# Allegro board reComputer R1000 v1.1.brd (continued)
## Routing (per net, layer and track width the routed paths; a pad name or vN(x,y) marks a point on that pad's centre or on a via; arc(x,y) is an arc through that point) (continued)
GND_ISO: length 185.1
  TOP w0.305: v1(85.85,15.4) 85.57,15.12 C138.2 ; v1(93.32,15.53) 93.32,15.4 94.19,14.54 D39.1 ; D34.1 v1(68.74,17.43) ; C141.2 74.55,14.99 v1(74.96,15.4) ; C143.2 v1(63.91,13.15)
  TOP w0.375: 68.65,10.76 R149.2 ; R149.2 69.35,11.46 ; R149.2 70.05,10.76 ; 74.94,14.51 C141.2 74.55,14.09 ; J21.3 98.48,6 ; J21.3 95.97,6 ; J21.3 97.22,4.74 ; J21.3 97.22,7.26 ; J23.3 74.98,6 ; J23.3 72.47,6 ; J23.3 73.72,4.74 ; J23.3 73.72,7.26 ; 85.88,9.87 D44.1 ; D44.1 84.61,11.26 ; D44.1 87.15,11.26 ; 85.57,13.8 C138.2 85.97,14.21 ; 94.67,13.27 D39.1 96.07,14.54 ; 85.47,4.74 J22.3 ; J22.3 84.22,6 ; J22.3 85.47,7.26 ; J22.3 86.73,6 ; 87.16,10.63 R132.2 88.56,10.63 ; 68.6,10.76 C134.2 67.9,11.46
  TOP w0.508: D44.1 85.27,10.65 v1(85.27,9.69) ; R141.2 v1(76.33,9.53) ; R132.2 v1(87.86,9.72) ; D48.1 v1(68.96,4.03)
  LYR2_GND w0.375: 72.47,6 J23.3 ; J23.3 73.72,7.26 ; J23.3 73.72,4.74 ; J23.3 74.98,6 ; 85.47,4.74 J22.3 ; J22.3 84.22,6 ; J22.3 86.73,6 ; J22.3 85.47,7.26 ; 97.22,4.74 J21.3 ; J21.3 97.22,7.26 ; J21.3 95.97,6 ; J21.3 98.48,6 ; 59.75,18.3 U22.3 59.04,19.26
  LYR3 w0.375: 97.22,4.74 J21.3 ; J21.3 97.22,7.26 ; J21.3 95.97,6 ; J21.3 98.48,6 ; J23.3 73.72,7.26 ; J23.3 74.98,6 ; J23.3 73.72,4.74 ; J23.3 72.47,6 ; 85.47,4.74 J22.3 ; J22.3 86.73,6 ; J22.3 85.47,7.26 ; J22.3 84.22,6 ; 59.75,18.3 U22.3 59.04,19.26
  LYR4_GND w0.375: 85.47,4.74 J22.3 ; J22.3 84.22,6 ; J22.3 86.73,6 ; J22.3 85.47,7.26 ; 72.47,6 J23.3 ; J23.3 73.72,4.74 ; J23.3 73.72,7.26 ; J23.3 74.98,6 ; 97.22,4.74 J21.3 ; J21.3 97.22,7.26 ; J21.3 98.48,6 ; J21.3 95.97,6 ; 59.04,19.26 U22.3 59.75,18.3
  LYR5_PWR w0.375: J22.3 85.47,7.26 ; J22.3 85.47,4.74 ; J22.3 86.73,6 ; J22.3 84.22,6 ; 72.47,6 J23.3 ; J23.3 73.72,7.26 ; J23.3 73.72,4.74 ; J23.3 74.98,6 ; 95.97,6 J21.3 ; J21.3 97.22,7.26 ; J21.3 98.48,6 ; J21.3 97.22,4.74 ; 59.75,18.3 U22.3 59.04,19.26
  LYR7_GND w0.375: 59.75,18.3 U22.3 59.04,19.26 ; 72.47,6 J23.3 ; J23.3 74.98,6 ; J23.3 73.72,7.26 ; J23.3 73.72,4.74 ; 95.97,6 J21.3 ; J21.3 97.22,7.26 ; J21.3 98.48,6 ; J21.3 97.22,4.74 ; 84.22,6 J22.3 ; J22.3 86.73,6 ; J22.3 85.47,7.26 ; J22.3 85.47,4.74
  BOTTOM w0.305: U27.9 v1(71.58,15.71) ; v1(70.64,15.73) 70.31,15.4 U27.10 ; U26.10 v1(81.33,15.48) ; U24.10 92.29,15.29 v1(92.53,15.53) ; U24.9 93.56,15.16 93.32,15.4 v1(93.32,15.53) ; U26.15 74.98,15.38 v1(74.96,15.4) ; U26.9 v1(82.6,15.51) ; U27.15 63.96,13.2 v1(63.91,13.15) ; 85.94,15.32 v1(85.85,15.4)
  BOTTOM w0.375: 84.22,6 J22.3 ; J22.3 85.47,4.74 ; J22.3 85.47,7.26 ; J22.3 86.73,6 ; 97.22,4.74 J21.3 ; J21.3 95.97,6 ; J21.3 97.22,7.26 ; J21.3 98.48,6 ; U27.10 70.86,14.3 ; U27.10 69.76,14.3 ; U27.10 70.31,13.25 ; 71.03,14.3 U27.9 ; U27.9 72.13,14.3 ; U27.9 71.58,13.25 ; 72.47,6 J23.3 ; J23.3 73.72,7.26 ; J23.3 74.98,6 ; J23.3 73.72,4.74 ; 93.01,14.3 U24.9 ; U24.9 94.12,14.3 ; U24.9 93.56,13.24 ; 80.78,14.3 U26.10 ; U26.10 81.33,13.25 ; U26.10 81.89,14.3 ; 91.43,11.26 D41.2 92.7,12.66 ; 59.75,18.3 U22.3 59.04,19.26 ; 82.6,13.25 U26.9 ; U26.9 83.16,14.3 ; U26.9 82.05,14.3 ; U26.15 75.54,14.3 ; U26.15 74.98,13.25 ; U26.15 74.43,14.3 ; 92.29,13.24 U24.10 ; U24.10 92.85,14.3 ; U24.10 91.74,14.3 ; 63.41,14.3 U27.15 ; U27.15 63.96,15.36 ; U27.15 64.51,14.3 ; 78.59,11.26 D46.2 79.86,12.66 ; 86.5,14.3 U24.15 85.39,14.3
  BOTTOM w0.508: D46.2 79.86,11.19 80.5,10.55 v1(80.5,9.71) ; U24.15 85.94,15.32 ; v1(92.59,9.49) 92.7,9.6 D41.2 ; D36.2 105.62,12.76 105.13,13.25 v1(100.69,13.25)
  vias: v1(57.69,21.93) v1(57.71,21.47) v1(57.71,21.02) v1(57.69,20.56) v1(72.77,3.49) v1(76.33,3.42) v1(79.71,3.44) v1(82.12,3.49) v1(84.28,3.42) v1(87.15,3.44) v1(90.17,3.57) v1(92.71,3.54) v1(94.82,3.57) v1(98.02,3.49) v1(100.64,4.03)
VCC_USB1:
  vias: v1(98.45,54.52) v1(98.45,54.06) v1(98.99,54.52) v1(99.01,54.06) v1(108.94,74.99) v1(108.94,74.56) v1(109.37,74.99) v1(109.37,74.56)
VCC_USB2:
  vias: v1(101.35,52.62) v1(101.35,52.18) v1(101.86,52.62) v1(101.86,52.18) v1(111.91,70.45) v1(111.94,70.01) v1(112.37,70.45) v1(112.4,70.01)
VDD18CORE: length 20.7
  TOP w0.254: v1(58.77,36.83) C6.1 58.47,36.09 C19.1 57.28,35.48 U4.15 ; C14.1 44.95,34.06 v1(45.53,33.48) U4.38
  LYR6 w0.305: v1(45.53,33.48) 46.97,34.91 56.85,34.91 v1(58.77,36.83)
VDD18ETHPLL: length 3.3
  TOP w0.254: FB3.1 43.36,28.14 C502.1 44.67,28.48 U4.48
VDD18USBPLL: length 14.2
  TOP w0.254: U4.62 53.34,28.39 v1(52.96,28.76)
  TOP w0.305: v1(43.72,25.74) 43.72,25.56 43.41,25.26 C501.1 FB3.2
  LYR6 w0.381: v1(52.96,28.76) 52.33,29.4 47.37,29.4 v1(43.72,25.74)
VDD33_HUB1: length 53.1
  TOP w0.254: R78.1 50.68,25.46 v1(50.75,25.39) ; C46.1 v1(44.85,33.49) ; C46.1 44.91,32.98 45.34,32.98 ; C46.1 44.85,32.75 44.34,32.24 R43.1 ; 45.52,32.98 45.52,32.8 ; 45.52,32.98 45.69,32.98 ; 45.52,32.98 45.34,32.98 ; 45.52,32.8 45.69,32.98 ; 45.52,32.8 45.34,32.98 ; 45.52,32.8 45.52,32.65 45.69,32.48 U4.40 ; v1(46.81,38.18) 46.97,38.02 48.48,38.02 49.34,37.16 U4.27 ; C47.1 56.44,36.6 v1(56.37,36.68) 56.37,36.86 55.92,37.3 53.57,37.3 53.34,37.07 U4.19 ; 45.69,32.98 U4.39 ; R41.1 57.51,33.05 R44.1 v1(58.24,32.52) ; v1(47.91,25.26) 48.04,25.39 R81.1 ; R79.1 R80.1 49,25.41 v1(49.13,25.28) ; U4.46 44.93,29.48 C45.1 44.85,29.91 v1(44.83,29.93) ; C41.1 44.79,35.98 U4.33
  LYR6 w0.381: v1(47.91,25.26) 49.1,25.26 v1(49.13,25.28) 50.65,25.28 v1(50.75,25.39) 50.75,25.01 51.13,24.62 56.42,24.62 58.85,27.06 v1(58.85,28.82)
  BOTTOM w0.203: C40.1 46.54,38.01 46.01,37.49 R50.2
  BOTTOM w0.254: C40.1 v1(46.81,38.18)
  BOTTOM w0.305: v1(44.07,36.26) 43.82,36 43.81,36 42.48,36 40.54,37.93 29.77,37.93 28.72,36.88 C500.1 28.73,36.65 U33.8
  vias: v1(44.07,36.71) v1(44.5,36.71) v1(44.5,36.26) v1(58.42,28.82)
VDD33_HUB2: length 25.5
  TOP w0.305: C63.1 96.88,65.54 v1(96.9,65.57) U5.29 ; U5.23 94.57,69.45 94.13,69.02 94.13,66.53 v1(94.8,65.87) 94.82,65.85 C64.1 ; v1(97.26,74.43) R66.2 R61.2 R67.2 R62.2 R68.2 ; U5.15 v1(97.9,73.21) 97.92,73.22 C67.1 98.18,73.55 98.69,74.06 R60.2 R65.2 ; U5.5 v1(102.36,69.45) ; U5.36 100.4,66.31 100.51,66.2 v1(100.51,65.87) ; U5.10 v1(100.4,72.95)
  BOTTOM w0.305: R51.1 76.57,74.09 v1(77.11,74.63) C68.1 U6.4 ; v1(100.4,72.95) 100.4,71.89 C62.1 ; R59.1 R52.1 v1(83.19,74.08) ; R63.2 86.58,74.48 C73.1 v1(86.07,74.49) ; C65.1 v1(102.36,69.45) ; C66.1 100.97,66.26 100.61,65.9 100.54,65.9 v1(100.51,65.87)
  vias: v1(101.37,73.16) v1(101.81,73.16) v1(102.24,73.16)
VDD33A_HUB1: length 10.6
  TOP w0.254: v1(51.31,25.21) 51.33,25.23 51.33,25.59 C50.1 51.33,26.23 50.84,26.72 U4.57 ; U4.10 55.96,32.98 v1(56.39,32.55) ; U4.51 v1(47.84,28.47) ; v1(49.41,28.46) 49.34,28.39 U4.54 ; v1(45.44,25.79) 45.87,26.22 C53.1 46.21,26.56 46.84,27.19 U4.49 ; C54.1 v1(56.42,30.5) 56.39,30.48 U4.5 ; 56.46,26.19 C52.1
  TOP w0.305: C51.1 56.4,32.54 v1(56.39,32.55)
  vias: v1(56.77,28.71) v1(57.23,28.71)
VDD_3V3_PCIE: length 11.3
  TOP w0.381: v1(24.89,48.32) 19.23,48.32 18.7,48.86 v1(18.67,48.86)
  BOTTOM w0.254: C168.1 25.01,47.93 25.53,47.41 R175.1
  BOTTOM w0.305: OSC1.1 OSC1.4 23.73,47.93 C168.1 v1(24.89,48.32)
  vias: v1(16.87,48.86) v1(17.3,48.86) v1(17.73,48.86) v1(18.16,48.86) v1(19.59,67.02) v1(19.56,66.51) v1(19.56,66.03) v1(19.92,69.4) v1(19.92,68.97) v1(20.07,67.02) v1(20.04,66.51) v1(20.04,66.03) v1(20.35,69.68) v1(20.35,69.28)
VDD_3V3_SYS: length 47.6
  TOP w0.203: C38.1 60.28,28.27 U3.9
  TOP w0.254: R654.1 65.83,36.37 66.04,36.59 v1(66.04,36.64) ; U19.8 v1(33.65,70.13)
  TOP w0.305: v1(61.04,28.43) 61.04,28.29 60.73,27.99 C38.1 ; R85.1 R88.1 R89.1 24.98,72.14 24.48,71.63 24.48,70.37 ; v1(33.65,70.13) 33.63,70.11 C110.2
  TOP w0.508: D27.1 v1(10.51,75.99)
  LYR6 w0.305: v1(46.61,39.53) 49.38,39.53 50.57,40.73 58.7,40.73 61.52,43.55 61.52,48.03 v1(61.34,48.21)
  BOTTOM w0.305: R102.1 60.12,79.4 60.63,79.91 C107.1 ; C107.1 60.66,80.08 ; C107.1 v1(60.63,80.43) 60.63,81.06 60.95,81.38 U17.8 ; C30.1 46.93,39.22 v1(46.61,39.53) 46.15,39.99 R653.1 ; C106.1 v1(16.85,20.28)
  BOTTOM w0.381: v1(40.57,29.25) 40.14,29.68 D25.1
  BOTTOM w0.508: R38.1 v1(16.77,76.49) ; FB9.1 35,18.83 v1(34.95,18.78)
  BOTTOM w0.635: J13.1 17.3,18.83 17.91,18.22 17.91,15.58 17.35,15.02 J13.7
  vias: v1(4.68,43.78) v1(5.11,43.78) v1(13.06,46.85) v1(13.06,46.39) v1(13.49,46.85) v1(13.49,46.39) v1(13.92,46.85) v1(13.92,46.39) v1(15.78,5.9) v1(15.78,5.42) v1(17.27,20.28) v1(23.37,70.73) v1(23.83,70.7) v1(40.54,28.82) v1(41.07,29.25) v1(41.07,28.82) v1(42.9,31.97) v1(42.9,31.53) v1(43.33,31.97) v1(43.33,31.53) v1(60.89,49.58) v1(60.89,49.1) v1(60.89,48.67) v1(60.89,48.21) v1(61.34,49.58) v1(61.34,49.1) v1(61.34,48.67) v1(64.52,27.55) v1(64.52,27.11) v1(72.32,25.77) v1(72.32,25.31) v1(72.75,25.77) v1(72.75,25.31) v1(103.02,75.53) v1(103.02,75.09) v1(103.28,74.71) v1(103.79,74.71)
VDD_5V_OUT:
  vias: v1(36.15,79.69) v1(36.17,79.23) v1(36.6,79.72) v1(36.63,79.23)
VDD_5V_OUT_CTL: length 4.1
  TOP w0.121: v1(31.96,71.89) 31.92,71.86 U12.12
  BOTTOM w0.121: v1(31.96,71.89) 31.4,72.45 U31.4 30.7,73.36 30.43,73.09 R174.1
VDD_5V_SYS: length 32.8
  LYR6 w0.305: v1(64.75,37.88) 67.39,40.52 76.94,40.52 81.13,44.72 v1(81.13,47.89)
  BOTTOM w0.254: 9.73,36.41 9.72,36.4 R33.2
  BOTTOM w0.305: v1(18.44,73) C108.1 17.88,73 17.61,72.74 U18.5 16.88,72.74 16.41,72.27 14.33,72.27 13.9,72.71 R105.1 11.26,72.83 R104.1 ; v1(64.75,37.88) 64.72,37.91 64.62,37.91 64.42,37.91 63.9,38.43 R652.1 63.89,38.49 C17.1
  vias: v1(5.62,38.82) v1(5.62,38.32) v1(6.12,38.82) v1(6.12,38.32) v1(17.45,73.14) v1(18.06,72.61) v1(25.07,74.74) v1(25.07,74.31) v1(25.5,74.74) v1(25.5,74.31) v1(52.02,78.14) v1(52.02,77.71) v1(52.02,77.28) v1(52.45,78.14) v1(52.45,77.71) v1(52.45,77.28) v1(52.89,78.14) v1(52.89,77.71) v1(70,25.51) v1(70,25.08) v1(70.49,25.51) v1(70.49,25.08) v1(80.62,49.29) v1(80.62,48.83) v1(80.62,48.35) v1(80.65,47.89) v1(80.93,67.55) v1(80.95,67.07) v1(81.13,49.29) v1(81.13,48.83) v1(81.13,48.35) v1(81.38,67.55) v1(81.41,67.07) v1(81.84,67.55) v1(81.87,67.07) v1(82.07,57.42) v1(82.04,56.91) v1(82.07,56.4) v1(82.07,55.94) v1(82.3,67.55) v1(82.32,67.07) v1(82.58,57.42) v1(82.55,56.91) v1(82.58,56.4) v1(82.58,55.94) v1(94.39,55.89) v1(96.14,51.35) v1(96.52,50.94) v1(100.1,52.62) v1(100.1,52.18) v1(100.61,52.62) v1(100.61,52.18) v1(108.51,72.83) v1(108.51,72.33) v1(108.99,72.83) v1(108.99,72.33)
VDD_IN:
  vias: v1(17.53,81.09) v1(18.04,81.09) v1(18.52,81.06) v1(18.52,80.56) v1(31.98,78.85) v1(31.98,78.4) v1(31.98,77.94) v1(42.52,53.76) v1(42.98,54.24) v1(42.98,53.76) v1(61.62,40.4) v1(61.62,39.94) v1(61.62,39.48) v1(62.05,40.4) v1(62.05,39.94) v1(62.05,39.48) v1(62.49,40.4) v1(62.49,39.94) v1(62.49,39.48) v1(63.6,53.56) v1(64.09,53.56) v1(64.59,53.56) v1(70.59,29.91) v1(70.59,29.45) v1(70.59,28.99) v1(71.05,29.91) v1(71.05,29.45) v1(71.05,28.99) v1(71.5,29.93) v1(71.5,29.45) v1(82.25,38.77) v1(82.25,38.32) v1(82.25,37.86) v1(82.68,38.77) v1(82.68,38.32) v1(82.68,37.86) v1(83.11,38.77) v1(83.11,38.32) v1(83.11,37.86)
VDD_LTE_3V3: length 6.4
  BOTTOM w0.305: v1(107.37,33.31) 107.37,32.65 107.65,32.37 109.5,32.37 110.19,33.06 TP31.1
  BOTTOM w0.381: J15.41 v1(84.55,25.86) ; J15.39 v1(85.35,25.82)
  vias: v1(34.95,65.92) v1(35.38,65.92) v1(76.2,66.86) v1(76.71,66.84) v1(79.53,35.29) v1(79.53,34.86) v1(79.53,34.43) v1(79.53,34) v1(106.83,33.82) v1(106.83,33.31) v1(107.37,33.82)
VDD_OUT:
  vias: v1(37.85,79.69) v1(37.85,79.26) v1(38.36,79.69) v1(38.36,79.26)
VDD_OUT_CTL: length 22.1
  TOP w0.121: U12.11 v1(32.36,71.36) ; Q5.1 28.25,76.92 R164.1 26.95,79.18 v1(26.75,79.39)
  LYR3 w0.121: v1(23.9,71.54) 23.9,76.54 v1(26.75,79.39)
  BOTTOM w0.121: v1(32.36,71.36) 27.1,71.36 26.62,70.88 24.56,70.88 v1(23.9,71.54)
VDD_RTC: length 11.8
  TOP w0.305: 13.84,74.38 13.85,74.39 C105.1 14.19,74.07 14.15,74.03
  TOP w0.508: U16.8 14.66,72.3 14.15,72.81 14.15,74.03 ; 13.84,74.38 C104.1 12.15,74.38 D28.2 12.15,76.09 12.77,76.71 D27.2 D29.2 v1(13.83,78.1)
  BOTTOM w0.508: v1(13.83,78.1) 13.58,78.1 TP22.1
VDD_UPS: length 10.2
  BOTTOM w0.508: 85.42,45.9 84.15,44.63 Q1.5 ; 85.42,45.9 Q1.9 85.42,47.17 ; 85.42,45.9 Q1.6 ; 85.42,47.17 Q1.7 ; 85.42,47.17 84.15,48.44 Q1.8
  vias: v1(82.68,43.12) v1(82.68,42.66) v1(82.68,42.2) v1(82.68,41.72) v1(83.14,43.12) v1(83.14,42.66) v1(83.14,42.2) v1(83.14,41.72)
CM4_GPIO24: length 1.6
  TOP w0.121: J4.45 v1(65,76.41)
  BOTTOM w0.121: TP38.1 65.62,75.8 v1(65,76.41)
CM4_GPIO26: length 4.9
  TOP w0.121: v1(69.43,71.78) 69.4,71.81 J4.24
  BOTTOM w0.121: TP39.1 72.1,72.66 70.31,72.66 v1(69.43,71.78)
CM4_GPIO27: length 2.1
  TOP w0.121: v1(64.21,73.65) 64.6,73.26 J4.48
  BOTTOM w0.121: v1(64.21,73.65) 64.67,73.65 TP40.1
CM4_GPIO_VREF: length 43.6
  TOP w0.203: J4.78 v1(58.6,72.07)
  TOP w0.305: R30.1 R31.1 v1(35.76,68.74) ; v1(61.34,80.71) 61.66,80.39 R106.1 R107.1 R178.1 R177.1
  LYR3 w0.305: v1(61.34,80.71) 61.34,79.36 59.54,77.56 v1(59.54,73.42)
  BOTTOM w0.305: v1(35.76,68.74) 36.57,69.55 46.32,69.55 48.16,71.39 57.91,71.39 v1(58.6,72.07) 58.88,72.35 C35.2 ; C35.2 59.03,72.9 v1(59.54,73.42) 60.3,74.18 TP16.1 ; C35.2 58.76,72.78 R29.1
CM4_IIC0_SCL: length 98.7
  TOP w0.121: v1(33.58,72.22) 33.56,72.2 33.56,71.56 33.99,71.13 U19.6 ; R27.1 v1(36.79,67.51) ; v1(66.7,79.51) 66.84,79.66 R177.2
  LYR3 w0.121: v1(33.58,72.22) 34.17,71.64 34.17,69.96 34.92,69.2 36.31,69.2 37.01,68.5 37.01,67.73 v1(36.79,67.51) ; v1(9.71,54.44) 7.19,56.96 7.19,65.65 v1(7.57,66.03)
  LYR6 w0.121: v1(7.57,66.03) 8.09,66.54 16.41,66.54 23.04,73.17 28.05,73.17 29.71,74.83 30.97,74.83 v1(33.58,72.22) 34.04,71.77 36.47,71.77 38.66,69.58 45.38,69.58 50.44,74.64 51.47,74.64 54.29,77.45 58.22,77.45 59.09,78.32 65.65,78.32 66.7,79.37 v1(66.7,79.51)
  BOTTOM w0.121: J24.20 6.83,53.04 7.44,53.66 7.44,54.22 7.74,54.51 U34.7 U34.4 9.64,54.51 v1(9.71,54.44)
CM4_IIC0_SDA: length 95.4
  TOP w0.121: v1(37.32,68.74) 37.25,68.74 37.13,68.62 R28.1 ; v1(34.29,72.3) 34.29,71.79 34.46,71.63 U19.5 ; R178.2 v1(66.08,79.32)
  LYR3 w0.121: v1(37.32,68.74) 36.6,69.46 35.13,69.46 34.5,70.09 34.5,72.1 v1(34.29,72.3) ; v1(7.55,66.79) 6.71,65.95 6.71,56.76 v1(9.71,53.76)
  LYR6 w0.121: v1(7.55,66.79) 16.31,66.79 22.94,73.42 27.94,73.42 29.61,75.08 31.51,75.08 v1(34.29,72.3) 36.29,72.3 38.75,69.84 45.29,69.84 50.41,74.96 51.44,74.96 54.18,77.7 58.12,77.7 59.02,78.6 65.36,78.6 v1(66.08,79.32)
  BOTTOM w0.121: J24.21 7.01,52.54 7.7,53.22 7.7,53.89 7.82,54.01 U34.6 U34.5 9.45,54.01 v1(9.71,53.76)
CM4_IIC5_SCL: length 27
  TOP w0.121: R30.2 36.27,66.08 v1(36.38,65.98) 36.45,65.9 R24.1 ; R88.2 26.32,72.83 v1(26.79,72.36) 27.29,71.86 U12.19
  LYR3 w0.121: v1(25.68,75.88) 26.55,75.02 26.55,72.61 v1(26.79,72.36) 27.05,72.1 v1(27.05,65.42)
  LYR6 w0.121: v1(36.38,65.98) 36.35,65.95 36.35,65.54 36.05,65.24 27.18,65.24 27.05,65.37 v1(27.05,65.42)
  BOTTOM w0.121: J61.9 26.11,76.31 v1(25.68,75.88)
CM4_IIC5_SDA: length 28.2
  TOP w0.121: R31.2 v1(36.61,68.3) ; U12.20 27.08,71.36 v1(26.6,71.84) 26.3,72.14 R89.2 ; R25.2 v1(36.75,66.7)
  LYR3 w0.121: v1(36.75,66.7) 36.3,67.14 36.3,67.98 v1(36.61,68.3) ; v1(24.87,76.01) 26.11,74.76 26.11,72.33 v1(26.6,71.84) 26.67,71.77 26.67,65.98 v1(26.55,65.85)
  LYR6 w0.121: v1(36.75,66.7) 36.18,66.7 35.92,66.43 35.92,65.75 35.66,65.49 27.82,65.49 27.46,65.85 v1(26.55,65.85)
  BOTTOM w0.121: J61.11 24.84,76.03 v1(24.87,76.01)
CM4_IIC6_SCL: length 120.8
  TOP w0.121: J2.11 63.6,35.06 v1(63.27,35.39) ; U16.6 16.89,69.76 v1(16.94,69.81) ; R106.2 v1(64.62,79.29) R23.2
  LYR3 w0.121: v1(64.62,79.29) 64.57,79.23 64.57,74.94 63.81,74.18 63.81,73.29 65.1,72 65.1,64.58 65.89,63.79 65.89,38.29 63.43,35.83 63.43,35.55 v1(63.27,35.39) 62.87,35.8 57.51,35.8 56.01,34.3 56.01,33.79 56.26,33.54 56.67,33.54 v1(57,33.87)
  LYR6 w0.121: v1(16.94,69.81) 16.94,70.73 20.13,73.91 27.74,73.91 29.4,75.58 33.71,75.58 38.92,70.37 44.94,70.37 50.19,75.63 51.41,75.63 53.98,78.19 57.91,78.19 59.01,79.29 v1(64.62,79.29)
  BOTTOM w0.121: v1(57,33.87) 56.84,34.03 J14.30 ; U17.6 64.18,78.84 v1(64.62,79.29)
CM4_IIC6_SDA: length 122.2
  TOP w0.121: R22.1 v1(65.38,79.31) R107.2 ; J2.13 62.33,35.17 v1(62.56,35.39) ; v1(16.89,68.49) U16.5
  LYR3 w0.121: 65.37,79.3 v1(65.38,79.31) ; 65.37,79.3 65.33,79.26 ; 65.37,79.3 65.37,75.31 64.59,74.54 64.59,72.96 65.41,72.15 65.41,64.68 66.19,63.89 66.19,38.16 63.73,35.7 63.73,35.3 63.44,35 62.9,35 62.56,35.34 v1(62.56,35.39) 57.79,35.39 v1(56.42,34.02)
  LYR6 w0.121: v1(65.38,79.31) 64.97,78.89 58.97,78.89 58.02,77.95 54.08,77.95 51.37,75.24 50.34,75.24 45.19,70.09 38.85,70.09 33.61,75.33 29.5,75.33 27.84,73.67 20.32,73.67 17.43,70.78 17.43,69.02 v1(16.89,68.49)
  BOTTOM w0.121: J14.32 56.04,34.27 56.29,34.02 v1(56.42,34.02) ; U17.5 63.64,77.57 v1(65.38,79.31)
CM4_SPI1_CE0: length 104.4
  TOP w0.203: J4.49 v1(64.2,75.12)
  LYR3 w0.121: v1(50.47,73.6) 50.24,73.37 50.24,72.63 43.87,66.26 43.87,53.17 34.95,44.25 34.95,31.49 39.46,26.99 39.46,25.14 40.01,24.59 40.01,22.52 39.42,21.93 v1(39.42,20.13)
  LYR6 w0.121: v1(20.12,13.47) 22.28,15.63 28.5,15.63 32.11,19.24 34.78,19.24 35.66,20.13 v1(39.42,20.13)
  BOTTOM w0.121: J13.9 19.84,13.75 v1(20.12,13.47) ; v1(64.2,75.12) 63.74,75.58 54.03,75.58 53.14,74.69 51.26,74.69 50.47,73.9 v1(50.47,73.6)
CM4_SPI1_CE1: length 77.2
  TOP w0.121: J4.50 v1(64.2,72.1)
  LYR3 w0.121: v1(41.94,25.34) 41.33,25.95 41.33,27.27 36.65,31.94 36.65,40.74 37.67,41.75 37.67,43.88 45.67,51.88 45.67,65.75 47.45,67.53 51.72,67.53 53.16,68.97 v1(53.16,70.88)
  BOTTOM w0.121: v1(64.2,72.1) 64.19,72.1 63.48,71.39 58.4,71.39 58.06,71.05 53.33,71.05 v1(53.16,70.88) ; v1(41.94,25.34) 45.72,25.34 46.05,25.67 48.26,25.67 48.44,25.85 J14.51
CM4_SPI1_MISO: length 121.7
  TOP w0.121: J4.26 v1(69,73.23)
  LYR3 w0.121: v1(42.32,21.04) 42.32,24.32 41.05,25.59 41.05,27.2 36.4,31.84 36.4,40.84 37.39,41.83 37.39,43.96 45.42,51.99 45.42,65.91 47.45,67.94 51.57,67.94 52.71,69.07 v1(52.71,69.46)
  LYR6 w0.121: v1(19.03,12.48) 20.53,12.48 22.63,14.59 28.55,14.59 31.9,17.94 39.95,17.94 42.32,20.31 v1(42.32,21.04)
  BOTTOM w0.121: J14.47 50.04,25.58 49.01,24.55 43.89,24.55 42.32,22.97 v1(42.32,21.04) ; v1(69,73.23) 68.18,72.4 68.18,71.77 66.63,70.22 61.83,70.22 61.06,69.46 v1(52.71,69.46) ; J13.11 v1(19.03,12.48)
CM4_SPI1_MOSI: length 127.6
  TOP w0.121: J4.27 v1(68.6,74.76)
  LYR3 w0.121: v1(41.7,21.04) 41.7,24.54 40.77,25.46 40.77,27.11 36.07,31.81 36.07,40.98 37.14,42.05 37.14,44.17 45.09,52.12 45.09,65.92 47.35,68.19 51.34,68.19 52.12,68.97 v1(52.12,70.85)
  LYR6 w0.121: v1(18.67,13.07) 20.42,13.07 22.48,15.12 28.48,15.12 31.65,18.3 39.8,18.3 41.7,20.19 v1(41.7,21.04)
  BOTTOM w0.121: J13.12 13.11,12.48 13.69,13.07 v1(18.67,13.07) ; v1(68.6,74.76) 68.6,74.17 67.4,72.97 67.4,72.15 66.35,71.11 58.47,71.11 58.16,70.8 53.7,70.8 53.34,70.44 52.54,70.44 v1(52.12,70.85) ; J14.49 49.24,25.95 48.16,24.87 42.82,24.87 41.7,23.75 v1(41.7,21.04)
CM4_SPI1_SCLK: length 125.5
  TOP w0.121: J4.25 v1(69,75.21)
  LYR3 w0.121: v1(51.49,70.32) 51.49,69.25 50.7,68.46 47.28,68.46 44.73,65.92 44.73,52.12 36.88,44.27 36.88,42.15 35.82,41.09 35.82,31.69 40.49,27.01 40.49,25.36 41.18,24.68 41.18,20.74 v1(41.28,20.64)
  LYR6 w0.121: v1(21.85,16.01) 28.43,16.01 32.06,19.65 34.72,19.65 35.71,20.64 v1(41.28,20.64)
  BOTTOM w0.121: v1(41.28,20.64) 41.3,20.61 42.6,20.61 42.95,20.97 42.95,22.95 43.95,23.95 47.8,23.95 48.13,23.62 R111.1 ; J13.10 13.52,13.75 14.1,14.34 20.17,14.34 v1(21.85,16.01) ; v1(69,75.21) 69,74.19 68.93,74.11 68.93,74.09 67.64,72.8 67.64,72.05 66.31,70.72 58.43,70.72 58.26,70.55 53.8,70.55 53.44,70.19 51.62,70.19 v1(51.49,70.32)
CM4_TPM_IRQ: length 111.5
  TOP w0.121: J4.29 v1(68.2,75.2)
  LYR3 w0.121: v1(10.42,18.83) 10.42,20.03 7.11,23.33 7.11,26.19 7.86,26.93 7.86,26.95 8.45,27.54 8.45,37.34 9.35,38.24 12.25,38.24 13,38.99 13,39.88 24.38,51.26 v1(24.38,67.91)
  LYR6 w0.121: v1(68.2,75.2) 67.8,75.6 64.71,75.6 64.49,75.82 54.58,75.82 47.55,68.8 38.38,68.8 35.66,71.51 33.61,71.51 32.84,72.27 30.13,72.27 27.36,69.51 26.62,69.51 25.02,67.91 v1(24.38,67.91)
  BOTTOM w0.121: J13.2 v1(10.42,18.83)
CM4_UART0_RXD: length 49.4
  TOP w0.121: v1(33,54.37) 33.29,54.07 R100.2 ; J4.51 63.8,74.99 v1(63.58,74.76)
  LYR3 w0.121: v1(34.98,60.9) 35.31,60.56 35.31,58.1 33,55.79 v1(33,54.37) ; 63.8,69.66 63.27,70.19 63.27,74.03 63.58,74.33
  LYR3 w0.127: v1(63.81,68.08) 63.8,68.09 63.8,69.66 ; v1(63.58,74.76) 63.58,74.33
  BOTTOM w0.121: v1(63.81,68.08) 63.4,67.68 49.82,67.68 48.58,66.43 48.58,65.08 47.81,64.32 40.82,64.32 37,60.49 35.41,60.49 35,60.9 v1(34.98,60.9)
CM4_UART0_TXD: length 50.8
  TOP w0.121: R99.2 33.53,52.56 v1(33.3,52.34) 33.3,52.09 D26.2 ; J4.55 v1(63,75.09)
  LYR3 w0.121: v1(35.77,60.9) 35.77,58.2 33.41,55.84 33.41,53.99 32.99,53.57 32.99,52.65 v1(33.3,52.34)
  LYR3 w0.127: v1(63,75.09) v1(63,68.08)
  BOTTOM w0.121: v1(63,68.08) 62.85,67.93 49.63,67.93 48.26,66.56 48.26,65.21 47.68,64.63 40.69,64.63 36.96,60.9 v1(35.77,60.9)
CM4_UART2_CTS: length 1.5
  TOP w0.121: J4.58 62.6,73.4 62.59,73.42 v1(62.59,73.47)
  BOTTOM w0.121: v1(62.59,73.47) 62.56,73.5 TP35.1
CM4_UART2_RTS: length 79.5
  TOP w0.121: J4.56 63,70.48 v1(62.31,69.79) ; R127.1 76.28,19.19 76.79,19.7 78.39,19.7 v1(78.56,19.87)
  LYR3 w0.121: v1(70.89,69.53) 70.9,69.54 83.08,69.54 84.53,68.08 84.53,37.25 81.03,33.74 81.03,29.02 79.12,27.11 79.12,20.43 v1(78.56,19.87)
  BOTTOM w0.121: v1(70.89,69.53) 70.73,69.69 70.17,69.69 70.12,69.64 63.85,69.64 63.71,69.79 v1(62.31,69.79)
CM4_UART2_RXD: length 78
  TOP w0.121: v1(67.06,76.31) 67,76.26 J4.35 ; R126.1 78.55,19.12 v1(79.25,19.82)
  LYR3 w0.121: v1(67.06,76.31) 67,76.26 67,73.93 67.44,73.49 67.44,70.75 v1(67.83,70.36) ; v1(71.48,70.29) 71.91,69.86 83.21,69.86 84.81,68.26 84.81,37.1 81.41,33.69 81.41,28.86 79.48,26.93 79.48,20.05 v1(79.25,19.82)
  BOTTOM w0.121: v1(71.48,70.29) 67.9,70.29 v1(67.83,70.36)
CM4_UART2_TXD: length 76.5
  TOP w0.121: R128.1 74.88,19.67 75.29,20.08 77.85,20.08 v1(78.56,20.79) ; J4.36 v1(67,73.29)
  LYR3 w0.121: v1(67.01,70.04) 67.01,70.12 67.13,70.24 67.13,73.16 v1(67,73.29) ; v1(78.56,20.79) 78.62,20.84 78.62,27.14 80.65,29.17 80.65,33.79 84.25,37.4 84.25,67.88 82.98,69.15 v1(71.43,69.15)
  BOTTOM w0.121: v1(71.43,69.15) 71.43,69.61 71.07,69.96 67.16,69.96 67.08,70.04 v1(67.01,70.04)
CM4_UART3_CTS: length 5
  TOP w0.121: J4.30 68.2,71.13 v1(68.23,71.11)
  BOTTOM w0.121: TP36.1 68.96,71.92 68.96,71.56 68.51,71.11 v1(68.23,71.11)
CM4_UART3_RTS: length 63.6
  TOP w0.121: J4.37 66.6,76.59 v1(66.66,76.66) ; R136.1 v1(76.28,20.48)
  LYR3 w0.121: v1(76.28,20.48) 75.87,20.89 75.87,27.27 77.27,28.66 77.27,43.75 71.6,49.42 71.6,66.41 69.93,68.08 69.93,73.18 70.07,73.32 70.07,74.66 68.02,76.7 66.71,76.7 v1(66.66,76.66)
CM4_UART3_RXD: length 93.9
  TOP w0.121: J4.34 v1(67.4,68.96) ; R134.1 v1(74.38,20.85) ; U25.4 v1(35.42,63)
  LYR3 w0.121: v1(69.47,68.97) 69.47,68.19 71.35,66.31 71.35,49.18 76.76,43.77 76.76,28.74 75.47,27.44 75.47,21.94 v1(74.38,20.85)
  BOTTOM w0.121: v1(35.42,63) 35.58,63.16 38.79,63.16 40.52,64.89 45.27,64.89 49.17,68.8 67.24,68.8 v1(67.4,68.96) 67.41,68.97 v1(69.47,68.97)
CM4_UART3_TXD: length 95
  TOP w0.121: J4.54 v1(63.4,69.35) ; R137.1 v1(77.41,20.85) ; U25.5 v1(34.77,62.98)
  LYR3 w0.121: v1(70.34,69.3) 70.34,68.02 71.95,66.4 71.95,49.42 77.52,43.85 77.52,28.38 76.79,27.65 76.79,21.48 v1(77.41,20.85)
  BOTTOM w0.121: v1(70.34,69.3) 70.26,69.38 63.43,69.38 v1(63.4,69.35) 63.1,69.05 49.08,69.05 45.16,65.14 40.26,65.14 38.59,63.46 35.26,63.46 v1(34.77,62.98)
CM4_UART4_CTS: length 5.9
  TOP w0.121: J4.44 65.4,72.09 64.87,71.56 v1(64.72,71.56)
  BOTTOM w0.121: v1(64.72,71.56) 65.05,71.56 65.67,72.18 65.67,72.38 65.67,73.42 66.26,74.01 66.66,74.01 66.66,74.01 TP37.1
CM4_UART4_RTS: length 56
  TOP w0.121: R145.1 v1(66.55,25.26) ; J4.38 66.6,71.79 66.47,71.67 v1(66.35,71.67)
  LYR3 w0.121: v1(66.55,25.26) 66.55,27.04 70.81,31.3 70.81,33.69 75.03,37.91 75.03,44.34 69.03,50.33 69.03,63.67 66.53,66.17 66.53,68.29 66.27,68.54 66.27,71.59 v1(66.35,71.67)
CM4_UART4_RXD: length 93.8
  TOP w0.121: U25.9 v1(34.12,58.99) ; v1(66.17,72.15) 66.2,72.18 J4.40 ; R144.1 v1(65.03,25.23)
  LYR3 w0.121: v1(66.17,72.15) 65.94,71.92 65.94,68.16 v1(66.07,68.03) 66.07,66.28 68.79,63.56 68.79,50.23 74.78,44.23 74.78,38.01 70.56,33.79 70.56,31.41 65.03,25.87 v1(65.03,25.23)
  BOTTOM w0.121: v1(66.07,68.03) 64.49,68.03 63.88,67.42 50.02,67.42 48.87,66.28 48.87,64.86 48.08,64.07 40.93,64.07 36.28,59.42 34.55,59.42 v1(34.12,58.99)
CM4_UART4_TXD: length 96.8
  TOP w0.121: J4.39 66.2,75.04 v1(66.32,74.92) ; R146.1 v1(67.41,25.16) ; U25.10 v1(34.77,58.97)
  LYR3 w0.121: v1(67.41,25.16) 67.41,27.52 71.08,31.19 71.08,33.58 75.3,37.79 75.3,44.45 69.31,50.44 69.31,63.78 67.01,66.08 v1(67.01,68.03) 67.01,68.29 66.55,68.74 66.55,70.8 66.89,71.14 66.89,72.42 66.12,73.19 66.12,74.71 v1(66.32,74.92)
  BOTTOM w0.121: v1(67.01,68.03) 66.53,67.55 64.72,67.55 64.32,67.14 50.19,67.14 49.18,66.13 49.18,64.76 48.2,63.78 41.05,63.78 36.23,58.97 v1(34.77,58.97)
CM4_UPS_DET: length 51.8
  TOP w0.121: J2.12 63.08,29.45 61.65,30.87 61.65,35.14 62.56,36.05 64.62,36.05 v1(64.65,36.03) 64.69,35.99 R654.2 ; v1(65.66,74.64) 65.8,74.78 J4.41
  LYR3 w0.121: v1(65.66,74.64) 65.66,64.83 66.5,63.99 66.5,37.88 v1(64.65,36.03)
DSI1_C_N: length 83.6
  TOP w0.095: J5.187 56.6,42.39 56.54,42.45 56.54,49.26 55.81,50 55.81,54.23 55.93,54.35 55.93,54.71 55.81,54.84 55.81,55.19 55.93,55.32 55.93,55.67 55.81,55.8 55.81,56.16 55.93,56.28 55.93,56.64 55.81,56.77 55.81,57.12 55.93,57.25 55.93,57.6 55.81,57.73 55.81,58.09 56.32,58.6 56.54,58.6 56.66,58.48 v1(56.87,58.48)
  LYR6 w0.102: v1(10.59,59.07) 10.37,59.07 10.27,58.97 9.35,58.97 8.16,57.77 8.16,54.06 9.17,53.05 31.14,53.05 31.55,53.45 34.09,53.45 35.36,54.72 46.38,54.72 48.36,56.7 53.65,56.7 55.53,58.58 56.55,58.58 56.66,58.48 v1(56.87,58.48)
  BOTTOM w0.095: v1(10.59,59.07) 10.37,59.07 10.26,58.95 9.78,58.95 9.67,59.06 U32.1 U32.10 7.72,59.06 7.61,58.95 6.75,58.95 6.66,59.04 J24.8
DSI1_C_P: length 83.6
  TOP w0.095: J5.189 56.2,42.39 56.26,42.45 56.26,49.15 55.53,49.88 55.53,58.2 56.2,58.88 56.54,58.88 56.66,58.99 v1(56.87,58.99)
  LYR6 w0.102: v1(10.59,58.56) 10.37,58.56 10.27,58.66 9.48,58.66 8.46,57.64 8.46,57.29 8.59,57.16 8.59,56.81 8.46,56.68 8.46,56.32 8.59,56.2 8.59,55.84 8.46,55.71 8.46,55.36 8.59,55.23 8.59,54.88 8.46,54.75 8.46,54.19 9.3,53.35 10.62,53.35 10.75,53.48 11.1,53.48 11.23,53.35 11.74,53.35 11.86,53.48 12.22,53.48 12.35,53.35 12.7,53.35 12.83,53.48 13.19,53.48 13.31,53.35 14.1,53.35 14.23,53.48 14.58,53.48 14.71,53.35 15.06,53.35 15.19,53.48 15.55,53.48 15.67,53.35 16.03,53.35 16.16,53.48 16.51,53.48 16.64,53.35 31.02,53.35 31.42,53.76 33.96,53.76 35.23,55.03 46.26,55.03 48.24,57.01 53.52,57.01 55.4,58.89 56.55,58.89 56.66,58.99 v1(56.87,58.99)
  BOTTOM w0.095: v1(10.59,58.56) 10.37,58.56 10.26,58.67 9.78,58.67 9.67,58.56 U32.2 U32.9 7.72,58.56 7.61,58.67 7.06,58.67 6.89,58.5 6.89,58.28 6.63,58.03 5.13,58.03 5.06,58.1 5.06,58.28 5.32,58.54 J24.9
DSI1_D0_N: length 99.9
  TOP w0.095: J5.175 59,42.39 58.94,42.45 58.94,49.02 60.53,50.61 60.53,53.16 60.66,53.29 60.66,53.64 60.53,53.77 60.53,54.13 60.79,54.39 60.97,54.39 61.22,54.64 61.22,54.82 61.47,55.07 61.65,55.07 61.91,55.32 61.91,55.5 62.16,55.75 62.16,56.56 62.28,56.69 62.28,57.05 62.16,57.17 62.16,57.53 62.36,57.73 62.59,57.73 62.7,57.62 v1(62.92,57.62)
  LYR6 w0.102: v1(10.66,62.05) 10.44,62.05 10.34,61.94 8.72,61.94 5.92,59.14 5.92,52.82 9.53,49.21 21.9,49.21 22.46,49.77 34.04,49.77 36.07,51.8 46.87,51.8 49.66,54.6 54.56,54.6 55.37,55.41 57.91,55.41 60.23,57.72 62.6,57.72 62.7,57.62 v1(62.92,57.62)
  BOTTOM w0.095: J24.2 6.61,62.04 6.71,61.93 7.72,61.93 7.83,62.04 U20.10 U20.1 9.67,62.04 9.78,61.93 10.33,61.93 10.44,62.05 v1(10.66,62.05)
DSI1_D0_P: length 99.9
  TOP w0.095: v1(62.92,58.13) 62.7,58.13 62.59,58.01 62.25,58.01 61.88,57.64 61.88,55.87 60.25,54.24 60.25,50.72 58.66,49.14 58.66,42.45 58.6,42.39 J5.177
  LYR6 w0.102: v1(10.66,61.54) 10.44,61.54 10.34,61.64 8.85,61.64 8.6,61.39 8.6,61.21 8.35,60.96 8.17,60.96 7.91,60.71 7.91,60.53 7.66,60.27 7.48,60.27 7.14,59.93 7.14,59.75 6.89,59.5 6.71,59.5 6.23,59.02 6.23,58.66 6.35,58.53 6.35,58.18 6.23,58.05 6.23,57.7 6.35,57.57 6.35,57.21 6.23,57.09 6.23,56.65 6.35,56.53 6.35,56.17 6.23,56.04 6.23,55.61 6.35,55.49 6.35,55.13 6.23,55 6.23,54.55 6.35,54.42 6.35,54.06 6.23,53.94 6.23,52.95 6.48,52.69 6.66,52.69 6.91,52.44 6.91,52.26 9.65,49.52 21.77,49.52 22.33,50.08 33.91,50.08 35.94,52.11 46.74,52.11 49.53,54.9 54.43,54.9 55.25,55.71 57.79,55.71 60.1,58.03 62.6,58.03 62.7,58.13 v1(62.92,58.13)
  BOTTOM w0.095: J24.3 5.32,61.54 5.06,61.28 5.06,61.12 5.16,61.02 6.76,61.02 6.96,61.23 6.96,61.51 7.11,61.65 7.66,61.65 7.77,61.54 U20.9 U20.2 9.67,61.54 9.78,61.65 10.33,61.65 10.44,61.54 v1(10.66,61.54)
DSI1_D1_N: length 84.9
  TOP w0.095: J5.181 57.8,42.39 57.74,42.45 57.74,49.54 56.87,50.41 56.87,52.8 57,52.93 57,53.29 56.87,53.41 56.87,53.77 57,53.9 57,54.25 56.87,54.38 56.87,54.73 57,54.86 57,55.22 56.87,55.34 56.87,55.7 57,55.83 57,56.18 56.87,56.31 56.87,56.67 57.03,56.82 57.18,56.82 57.29,56.7 v1(57.51,56.7)
  LYR6 w0.102: v1(57.51,56.7) 57.29,56.7 57.19,56.81 55.2,56.81 54.08,55.69 49.1,55.69 46.38,52.97 35.23,52.97 33.86,51.6 30.81,51.6 30.53,51.88 8.69,51.88 7.06,53.5 7.06,58.08 9.43,60.44 10.27,60.44 10.37,60.55 v1(10.59,60.55)
  BOTTOM w0.095: v1(10.59,60.55) 10.37,60.55 10.26,60.43 9.78,60.43 9.67,60.54 U20.4 U20.7 7.77,60.54 7.67,60.64 7.67,61.04 7.57,61.14 7.44,61.14 7.32,61.02 7.32,60.51 7.24,60.43 6.87,60.43 6.76,60.54 J24.5
DSI1_D1_P: length 85.1
  TOP w0.095: J5.183 57.4,42.39 57.46,42.45 57.46,49.42 56.59,50.29 56.59,56.78 56.91,57.1 57.18,57.1 57.29,57.21 v1(57.51,57.21)
  LYR6 w0.102: v1(10.59,60.04) 10.37,60.04 10.27,60.14 9.56,60.14 7.37,57.95 7.37,53.63 8.82,52.18 30.66,52.18 30.94,51.9 33.73,51.9 35.11,53.28 46.26,53.28 48.97,55.99 53.95,55.99 55.07,57.11 57.19,57.11 57.29,57.21 v1(57.51,57.21)
  BOTTOM w0.095: v1(10.59,60.04) 10.37,60.04 10.26,60.15 9.78,60.15 9.67,60.04 U20.5 U20.6 7.72,60.04 7.61,60.15 6.85,60.15 6.74,60.04 J24.6
DSI1_D2_N: length 74.8
  TOP w0.095: v1(53.49,58.43) 53.28,58.43 53.16,58.55 52.98,58.55 52.78,58.35 52.78,57.99 52.91,57.87 52.91,57.51 52.78,57.38 52.78,57.03 52.91,56.9 52.91,56.55 52.78,56.42 52.78,56.06 52.91,55.94 52.91,55.58 52.78,55.45 52.78,54.8 53.03,54.55 53.21,54.55 53.47,54.3 53.47,54.12 54.74,52.84 54.74,49.36 55.34,48.76 55.34,42.45 55.4,42.39 J5.193
  LYR6 w0.102: v1(53.49,58.43) 53.39,58.53 53.06,58.53 52.2,57.67 47.78,57.67 45.97,55.86 32.23,55.86 30.64,54.27 10.44,54.27 9.45,55.26 9.45,56.91 10.01,57.47 10.6,57.47 10.7,57.57 v1(10.91,57.57)
  BOTTOM w0.095: v1(10.91,57.57) 10.7,57.57 10.58,57.45 9.78,57.45 9.67,57.56 U32.4 U32.7 7.81,57.56 7.7,57.67 7.7,58.1 7.62,58.18 7.42,58.18 7.32,58.08 7.32,57.58 7.18,57.44 6.76,57.44 6.66,57.54 J24.11
DSI1_D2_P: length 75
  TOP w0.095: J5.195 55,42.39 55.06,42.45 55.06,48.65 54.46,49.25 54.46,52.73 52.5,54.68 52.5,58.47 52.86,58.83 53.16,58.83 53.28,58.94 v1(53.49,58.94)
  LYR6 w0.102: v1(53.49,58.94) 53.39,58.84 52.94,58.84 52.07,57.97 47.65,57.97 45.84,56.16 32.11,56.16 30.51,54.57 10.57,54.57 9.76,55.38 9.76,56.78 10.14,57.16 10.6,57.16 10.7,57.06 v1(10.91,57.06)
  BOTTOM w0.095: J24.12 6.69,57.04 6.81,57.16 7.62,57.16 7.72,57.06 U32.6 U32.5 9.67,57.06 9.78,57.17 10.58,57.17 10.7,57.06 v1(10.91,57.06)
DSI1_D3_N: length 74.8
  TOP w0.095: v1(51.08,59) 50.96,58.89 50.5,58.89 50.24,58.63 50.24,41.43 53.91,37.76 55.08,37.76 55.34,38.02 55.34,38.28 55.4,38.34 J5.194
  LYR6 w0.102: v1(51.08,59) 50.86,59 50.76,58.9 47.08,58.9 45.77,57.59 31.68,57.59 29.85,55.76 11.64,55.76 11.49,55.91 10.69,55.91 v1(10.59,56.01)
  BOTTOM w0.095: v1(10.59,56.01) 10.48,55.9 9.78,55.9 9.67,56.01 U34.1 U34.10 7.72,56.01 7.63,55.92 6.78,55.92 6.66,56.04 J24.14
DSI1_D3_P: length 74.8
  TOP w0.095: v1(51.08,58.5) 51.07,58.5 50.96,58.61 50.62,58.61 50.52,58.51 50.52,58.16 50.65,58.03 50.65,57.67 50.52,57.55 50.52,57.19 50.65,57.06 50.65,56.71 50.52,56.58 50.52,56.23 50.65,56.1 50.65,55.74 50.52,55.62 50.52,55.26 50.65,55.13 50.65,54.78 50.52,54.65 50.52,46.37 50.65,46.24 50.65,45.88 50.52,45.76 50.52,45.4 50.65,45.27 50.65,44.92 50.52,44.79 50.52,44.44 50.65,44.31 50.65,43.95 50.52,43.83 50.52,43.47 50.65,43.34 50.65,42.99 50.52,42.86 50.52,42.51 50.65,42.38 50.65,42.02 50.52,41.9 50.52,41.54 51.04,41.03 51.22,41.03 51.47,40.77 51.47,40.6 51.72,40.34 51.9,40.34 52.15,40.09 52.15,39.91 52.4,39.66 52.58,39.66 52.83,39.41 52.83,39.23 53.35,38.72 53.53,38.72 53.78,38.47 53.78,38.29 54.03,38.04 54.97,38.04 55.06,38.13 55.06,38.28 55,38.34 J5.196
  LYR6 w0.102: v1(51.08,58.5) 50.86,58.5 50.76,58.6 47.21,58.6 45.9,57.29 31.8,57.29 29.97,55.46 11.51,55.46 11.36,55.61 10.69,55.61 v1(10.59,55.5)
  BOTTOM w0.095: J24.15 5.34,55.54 5.11,55.31 5.11,55.1 5.23,54.98 6.89,54.98 7.04,55.13 7.04,55.51 7.17,55.64 7.53,55.64 7.66,55.51 U34.9 U34.2 9.67,55.51 9.78,55.62 10.48,55.62 v1(10.59,55.5)
EECLK: length 17.6
  TOP w0.121: U4.23 v1(51.34,37.27)
  LYR3 w0.121: v1(37.09,35.67) 37.44,35.67 38.08,36.31 40.77,36.31 41.86,37.4 46.28,37.4 46.76,36.92 50.98,36.92 v1(51.34,37.27)
  BOTTOM w0.121: v1(37.09,35.67) 36.79,35.38 U33.2
EECS: length 18.5
  TOP w0.121: v1(50.35,38.04) 50.35,37.96 50.84,37.47 U4.24
  LYR3 w0.121: v1(37.11,37.17) 37.16,37.17 37.77,36.56 40.66,36.56 41.8,37.71 45.01,37.71 45.85,38.54 47.76,38.54 48.69,37.6 49.91,37.6 v1(50.35,38.04)
  BOTTOM w0.121: U33.1 R573.1 36.99,37.05 v1(37.11,37.17)
EEDI: length 23.6
  TOP w0.121: U4.26 49.84,37.27 49.1,38.01 v1(49.1,38.06)
  LYR3 w0.121: v1(37.62,37.38) 37.62,37.27 38.05,36.84 40.54,36.84 41.68,37.98 44.94,37.98 45.75,38.8 48.36,38.8 v1(49.1,38.06)
  BOTTOM w0.121: U33.4 34.38,32.84 34.14,33.08 34.14,36.74 34.96,37.56 37.43,37.56 v1(37.62,37.38)
EEDO: length 23
  TOP w0.121: v1(49.71,38.04) 50.34,37.41 U4.25
  LYR3 w0.121: v1(37.11,35.09) 37.26,35.09 38.24,36.06 40.87,36.06 41.96,37.15 46.18,37.15 46.66,36.67 51.42,36.67 51.74,36.99 51.74,37.86 51.03,38.57 50.24,38.57 v1(49.71,38.04)
  BOTTOM w0.121: U33.3 36.44,34.11 36.68,34.35 36.68,34.66 v1(37.11,35.09)
EEPROM_WP: length 32.4
  TOP w0.121: U12.10 31.88,70.86 v1(31.9,70.88)
  BOTTOM w0.121: v1(31.9,70.88) 31.93,70.86 34.67,70.86 35.26,70.27 46.13,70.27 53.93,78.07 59.69,78.07 R103.2
ETHERNET_LED2: length 91
  TOP w0.121: v1(71.02,74.28) 70.6,74.7 J4.17
  LYR3 w0.121: v1(40.08,20.15) 39.83,20.41 39.83,21.83 40.41,22.41 40.41,24.65 39.72,25.35 39.72,27.08 35.21,31.59 35.21,41.18 36.32,42.3 36.32,44.64 44.15,52.46 44.15,66.15 50.75,72.76 v1(50.75,72.94)
  LYR6 w0.121: v1(71.02,74.28) 70.49,74.28 67.69,77.08 58.99,77.08 58.78,76.87 55.25,76.87 51.31,72.94 v1(50.75,72.94)
  BOTTOM w0.121: R155.1 37.41,18.5 39.09,18.5 40.08,19.49 v1(40.08,20.15)
ETHERNET_LED3: length 90
  TOP w0.121: J4.15 v1(71,75.09)
  LYR3 w0.121: v1(51.26,73.65) 51.26,72.83 44.4,65.98 44.4,52.26 36.63,44.49 36.63,42.25 35.49,41.11 35.49,31.66 40.13,27.01 40.13,25.31 40.69,24.75 40.69,22.29 40.44,22.03 40.44,20.54 v1(40.82,20.15)
  LYR6 w0.121: v1(51.26,73.65) 51.26,74.07 54.31,77.13 58.68,77.13 58.88,77.33 67.85,77.33 69.6,75.58 70.52,75.58 v1(71,75.09)
  BOTTOM w0.121: R160.1 39.61,17.98 40.82,19.19 v1(40.82,20.15)
ETHERNET_PAIR0_N: length 82
  TOP w0.095: J4.10 72.2,72.11 72.14,72.05 72.14,63.03 71.68,62.57 71.23,62.57 71.11,62.46 v1(70.89,62.46)
  BOTTOM w0.095: v1(70.89,62.46) 70.68,62.46 70.56,62.57 62.22,62.57 59.96,60.31 43.36,60.31 37.47,54.42 34.24,54.42 33,53.18 33,52.78 24.81,44.59 18.91,44.59 18.78,44.47 18.42,44.47 18.3,44.59 17.94,44.59 17.81,44.47 17.46,44.47 17.33,44.59 16.98,44.59 15.91,43.53 15.91,42.82 16.04,42.69 16.04,42.33 15.91,42.21 15.91,41.85 16.04,41.72 16.04,41.37 15.91,41.24 15.91,40.89 16.03,40.78 U29.2 U29.9 16.03,38.95 15.92,38.84 15.92,38.63 15.83,38.54 15.44,38.54 15.34,38.44 15.34,38.25 15.44,38.15 15.83,38.15 15.92,38.06 T1.3
ETHERNET_PAIR0_P: length 82
  TOP w0.095: v1(70.89,62.97) 71.11,62.97 71.23,62.85 71.57,62.85 71.86,63.15 71.86,63.5 71.74,63.63 71.74,63.99 71.86,64.11 71.86,64.47 71.74,64.6 71.74,64.95 71.86,65.08 71.86,65.43 71.74,65.56 71.74,65.92 71.86,66.04 71.86,66.64 71.74,66.76 71.74,67.12 71.86,67.25 71.86,72.05 71.8,72.11 J4.12
  BOTTOM w0.095: T1.1 13.92,38.03 14.58,38.7 15.2,38.7 15.52,39.01 15.52,39.35 U29.10 U29.1 15.53,40.78 15.64,40.89 15.64,43.65 16.86,44.87 24.7,44.87 32.72,52.9 32.72,53.29 34.12,54.7 37.35,54.7 43.24,60.59 59.84,60.59 62.11,62.85 70.56,62.85 70.68,62.97 v1(70.89,62.97)
ETHERNET_PAIR1_N: length 83.1
  TOP w0.095: v1(73.51,61.62) 73.29,61.62 73.18,61.73 72.93,61.73 72.67,61.99 72.67,62.65 73.06,63.04 73.06,72.05 73,72.11 J4.6
  BOTTOM w0.095: T1.6 18.92,38.17 18.47,38.62 17.75,38.62 17.53,38.85 U29.6 U29.5 17.53,40.78 17.42,40.89 17.42,41.24 17.54,41.37 17.54,41.72 17.42,41.85 17.42,42.27 17.54,42.39 17.54,42.75 17.42,42.88 17.42,43.23 17.81,43.62 18.16,43.62 18.29,43.5 18.65,43.5 18.77,43.62 19.43,43.62 19.56,43.5 19.92,43.5 20.04,43.62 25.58,43.62 34.83,52.87 37.62,52.87 44.2,59.45 60.4,59.45 62.69,61.73 73.18,61.73 73.29,61.62 v1(73.51,61.62)
ETHERNET_PAIR1_P: length 83
  TOP w0.095: v1(73.51,62.13) 73.29,62.13 73.18,62.01 73.04,62.01 72.95,62.11 72.95,62.53 73.34,62.92 73.34,63.64 73.47,63.77 73.47,64.12 73.34,64.25 73.34,64.6 73.47,64.73 73.47,65.09 73.34,65.21 73.34,65.57 73.47,65.7 73.47,66.05 73.34,66.18 73.34,66.59 73.47,66.71 73.47,67.07 73.34,67.19 73.34,72.05 73.4,72.11 J4.4
  BOTTOM w0.095: v1(73.51,62.13) 73.29,62.13 73.18,62.01 62.57,62.01 60.29,59.73 44.08,59.73 37.5,53.15 34.71,53.15 25.46,43.9 17.69,43.9 17.14,43.35 17.14,40.89 17.03,40.78 U29.4 U29.7 17.03,38.95 16.92,38.85 16.92,38.68 17.02,38.58 17.4,38.58 17.49,38.48 17.49,38.29 17.4,38.2 17.02,38.2 16.92,38.1 T1.4
ETHERNET_PAIR2_N: length 83
  TOP w0.095: v1(72.77,60.73) 72.99,60.73 73.11,60.84 73.91,60.84 74.53,61.47 74.53,73.27 73.87,73.93 72.8,73.93 72.14,74.58 72.14,75.13 72.2,75.19 J4.9
  BOTTOM w0.095: T1.9 21.92,38.14 21.83,38.23 21.43,38.23 21.34,38.33 21.34,38.52 21.43,38.61 21.83,38.61 21.92,38.71 21.92,39.02 21.99,39.1 U30.9 U30.2 21.99,40.93 21.88,41.04 21.88,42.26 22.28,42.66 22.63,42.66 22.76,42.53 23.12,42.53 23.24,42.66 23.6,42.66 23.73,42.53 24.08,42.53 24.21,42.66 24.56,42.66 24.69,42.53 25.05,42.53 25.17,42.66 25.99,42.66 26.24,42.91 26.42,42.91 26.67,43.16 26.67,43.34 35.36,52.03 38.37,52.03 44.03,57.7 61.22,57.7 64.37,60.84 72.44,60.84 72.56,60.73 v1(72.77,60.73)
ETHERNET_PAIR2_P: length 83.1
  TOP w0.095: v1(72.77,61.24) 72.99,61.24 73.11,61.12 73.79,61.12 74.25,61.58 74.25,62.04 74.12,62.17 74.12,62.52 74.25,62.65 74.25,63.79 74.12,63.92 74.12,64.27 74.25,64.4 74.25,64.76 74.12,64.88 74.12,65.24 74.25,65.37 74.25,65.72 74.12,65.85 74.12,66.2 74.25,66.33 74.25,73.15 73.75,73.65 72.68,73.65 71.86,74.47 71.86,75.13 71.8,75.19 J4.11
  BOTTOM w0.095: T1.7 19.92,38.14 20.42,38.65 21.07,38.65 21.49,39.07 U30.10 U30.1 21.49,40.93 21.6,41.04 21.6,42.38 22.16,42.94 25.87,42.94 35.24,52.31 38.25,52.31 43.92,57.97 61.1,57.97 64.25,61.12 72.44,61.12 72.56,61.24 v1(72.77,61.24)
ETHERNET_PAIR3_N: length 86.9
  TOP w0.095: v1(77.19,59.71) 76.98,59.71 76.86,59.83 75.83,59.83 75.34,60.32 75.34,73.38 74.21,74.51 73.32,74.51 73.06,74.77 73.06,75.13 73,75.19 J4.5
  BOTTOM w0.095: T1.12 24.92,38.52 24.74,38.7 23.84,38.7 23.84,38.7 23.49,39.05 U30.6 U30.5 23.49,40.93 23.38,41.04 23.38,41.35 23.68,41.64 24.03,41.64 24.16,41.52 24.51,41.52 24.64,41.64 25.07,41.64 25.2,41.52 25.55,41.52 25.68,41.64 26.42,41.64 26.67,41.89 26.85,41.89 27.1,42.15 27.1,42.33 27.35,42.58 27.53,42.58 27.78,42.83 27.78,43.01 35.89,51.12 38.8,51.12 44.47,56.78 55.67,56.78 56.53,55.92 58.49,55.92 59.21,56.64 63.54,56.64 64.82,57.92 72.44,57.92 74.35,59.83 76.86,59.83 76.98,59.71 v1(77.19,59.71)
ETHERNET_PAIR3_P: length 86.8
  TOP w0.095: v1(77.19,60.22) 76.98,60.22 76.86,60.11 75.95,60.11 75.62,60.44 75.62,60.79 75.75,60.92 75.75,61.28 75.62,61.4 75.62,61.94 75.75,62.06 75.75,62.42 75.62,62.55 75.62,63.13 75.75,63.26 75.75,63.61 75.62,63.74 75.62,64.15 75.75,64.27 75.75,64.63 75.62,64.76 75.62,73.49 74.33,74.79 73.44,74.79 73.34,74.88 73.34,75.13 73.4,75.19 J4.3
  BOTTOM w0.095: v1(77.19,60.22) 76.98,60.22 76.86,60.11 74.23,60.11 72.32,58.2 64.7,58.2 63.43,56.92 59.1,56.92 58.37,56.2 56.64,56.2 55.78,57.06 44.35,57.06 38.69,51.4 35.78,51.4 26.3,41.92 23.56,41.92 23.1,41.47 23.1,41.04 22.99,40.93 U30.4 U30.7 22.99,39.08 22.91,39 22.91,38.81 23.01,38.72 23.43,38.72 23.56,38.58 23.56,38.45 23.43,38.31 23.01,38.31 22.91,38.22 22.91,37.31 T1.10
ETHERNET_RX_N: length 17
  TOP w0.095: U4.53 48.84,27.25 48.73,27.14 48.73,26.53 R80.2 48.83,26.08 48.82,26.08 48.67,25.93 48.67,24.55 48.44,24.32 48.44,23.64 48.55,23.53 U11.4 U11.7 48.55,21.71 48.44,21.6 48.44,20.55 48.13,20.23 47.67,20.23 v1(47.55,20.12)
  LYR3 w0.102: J10.3 48.14,15.44 49.44,16.31 49.5,16.62 49.38,16.8 48.14,16.8 47.63,17.31 47.63,18.99 48.21,19.57 48.21,20.03 48.02,20.22 47.65,20.22 v1(47.55,20.12)
ETHERNET_RX_P: length 17.1
  TOP w0.095: v1(47.55,20.63) 47.67,20.51 48.01,20.51 48.16,20.66 48.16,20.89 48.06,20.98 47.93,20.98 47.83,21.08 47.83,21.27 47.93,21.37 48.06,21.37 48.16,21.46 48.16,21.6 48.05,21.71 U11.6 U11.5 48.05,23.53 48.16,23.64 48.16,24.43 48.39,24.66 48.39,25.91 48.04,26.25 R81.2 48.45,26.67 48.45,27.14 48.34,27.25 U4.52
  LYR3 w0.102: J10.6 49.84,16.93 49.63,16.97 49.54,17.11 48.26,17.11 47.93,17.44 47.93,18.86 48.52,19.44 48.52,20.15 48.14,20.53 47.65,20.53 v1(47.55,20.63)
ETHERNET_TX_N: length 15.7
  TOP w0.095: J10.1 45.72,16.58 45.84,16.62 45.85,16.62 45.92,16.58 45.97,16.53 47.17,16.53 48.01,17.37 48.01,18.64 49.94,20.57 49.94,21.6 50.05,21.71 U11.10 U11.1 50.05,23.53 49.94,23.64 49.94,24.38 50.32,24.76 50.32,25.9 50.5,26.08 50.5,26.08 R78.2 50.23,26.7 50.23,27.14 50.34,27.25 U4.56
ETHERNET_TX_P: length 15.6
  TOP w0.095: J10.2 45.75,17.83 45.56,17.45 45.72,17 46.09,16.81 46.09,16.81 47.06,16.81 47.73,17.49 47.73,18.76 49.66,20.69 49.66,21.6 49.55,21.71 U11.9 U11.2 49.55,23.53 49.66,23.64 49.66,24.5 50.04,24.88 50.04,25.9 49.88,26.06 49.88,26.06 R79.2 49.95,26.52 49.95,27.14 49.84,27.25 U4.55
EXT_RS485_1_A: length 21
  TOP w0.508: v1(99.16,12.64) 93.2,12.64 91.67,14.16 R125.2
  BOTTOM w0.508: D37.2 99.14,12.61 v1(99.16,12.64) ; D37.2 D36.1 ; D37.2 99.14,9.2 99.55,8.8 101.73,8.8 104.23,6.3 J21.1
EXT_RS485_1_B: length 17.3
  TOP w0.508: R130.2 94.66,10.48 D39.2 v1(94.67,9.03)
  BOTTOM w0.508: J21.2 100.72,7.49 100.21,8.01 98.1,8.01 95.08,11.03 D37.1 94.67,10.86 v1(94.67,9.03)
EXT_RS485_2_A: length 17.4
  TOP w0.508: R135.2 83.56,13.45 83.95,13.07 v1(86.29,13.07)
  BOTTOM w0.508: v1(86.29,13.07) 86.36,12.99 D42.2 ; J22.1 89.45,9.03 86.72,9.03 86.36,9.39 D42.2 ; D42.2 D41.1
EXT_RS485_2_B: length 18.6
  TOP w0.508: D44.2 81.82,9.26 v1(81.64,9.08) 81.38,8.83 78.74,8.83 78.09,9.48 R140.2
  BOTTOM w0.508: 82.3,10.96 82.3,9.74 v1(81.64,9.08) ; 82.3,10.96 D42.1 82.27,11.24 ; 82.3,10.96 84.99,8.27 86.71,8.27 J22.2
EXT_RS485_3_A: length 14.3
  TOP w0.508: v1(73.46,9.77) 73.66,9.77 R143.2
  BOTTOM w0.508: J23.1 80.73,6.3 78.28,8.75 74.48,8.75 v1(73.46,9.77) D47.2 D46.1
EXT_RS485_3_B: length 16.2
  TOP w0.508: R150.2 70.08,9.61 v1(69.88,9.61) 69.88,8.02 69.88,7.93 69.88,7.53 D48.2
  BOTTOM w0.508: D47.1 69.88,10.78 v1(69.88,9.61) 69.88,9.13 70.92,8.09 75.44,8.09 77.22,6.3 J23.2
EXT_VCC_9_36V: length 14.9
  TOP w0.305: R2.1 108.32,36.82 Q2.2 107.29,35.79 107.29,35.22 105.72,33.64 103.94,33.64 103.61,33.97 R3.1 97.43,35.18 97.41,35.17
  vias: v1(95.25,33.11) v1(95.25,32.65) v1(95.25,32.19) v1(95.71,33.11) v1(95.71,32.65) v1(95.71,32.19) v1(96.9,41.72) v1(96.9,41.26) v1(96.9,40.8) v1(97.36,41.72) v1(97.36,41.26) v1(97.36,40.8)
GLOBAL_EN: length 41.8
  TOP w0.121: v1(52.91,75.12) 53.8,75.12 54.2,75.52 J4.99
  BOTTOM w0.121: U18.4 18.58,74.04 18.85,73.77 18.85,73.37 22.05,70.17 31.85,70.17 32.21,70.52 34.6,70.52 35.16,69.96 46.17,69.96 51.15,74.94 52.63,74.94 52.81,75.12 v1(52.91,75.12)
HDMI0_5V:
  vias: v1(97.18,48.02) v1(97.18,47.59) v1(97.61,48.02) v1(97.61,47.59)
HDMI0_CEC: length 58.8
  TOP w0.121: U10.1 U10.10 103.06,47.17 103.02,47.14 v1(103.02,46.85) 103.1,46.77 103.1,43.81 J9.13 ; v1(65.48,53.58) 65.48,53.48 65.59,53.38 65.59,45.22 63.8,43.44 J5.151
  BOTTOM w0.121: v1(65.48,53.58) 93.14,53.58 98.1,48.63 101.6,48.63 103.02,47.21 v1(103.02,46.85)
HDMI0_CLK_N: length 75.7
  TOP w0.095: J5.190 56.2,39.31 56.26,39.37 56.26,39.54 55.97,39.83 53.4,39.83 51.36,41.87 51.36,47.61 51.23,47.74 51.23,48.09 51.36,48.22 51.36,48.58 51.23,48.7 51.23,49.06 51.36,49.19 51.36,49.54 51.23,49.67 51.23,50.02 51.36,50.15 51.36,50.51 51.23,50.63 51.23,50.99 51.36,51.12 51.36,51.47 51.23,51.6 51.23,51.95 51.36,52.08 51.36,52.44 51.92,53 51.92,53.32 51.73,53.52 51.59,53.52 51.48,53.4 v1(51.26,53.4)
  LYR6 w0.102: v1(51.26,53.4) 51.48,53.4 51.58,53.5 57.48,53.5 58.32,54.34 61.12,54.34 61.42,54.04 97.23,54.04 99.64,51.63 99.64,51.45 99.9,51.2 100.08,51.2 100.33,50.95 100.68,50.95 100.81,50.82 101.17,50.82 101.29,50.95 101.65,50.95 101.77,50.82 102.13,50.82 102.26,50.95 102.61,50.95 102.74,50.82 103.1,50.82 103.22,50.95 104.39,50.95 104.49,50.84 104.49,50.7 104.39,50.6 v1(104.39,50.38)
HDMI0_CLK_N1: length 9.6
  BOTTOM w0.095: J9.12 104.55,43.44 104.96,43.86 104.96,44 104.85,44.11 103.95,44.11 103.53,44.52 103.53,46.32 103.86,46.65 103.86,47.04 104.5,47.68 104.5,47.87 104.39,47.98 U9.5 U9.6 104.39,49.81 L22.4
HDMI0_CLK_P: length 75.7
  TOP w0.095: 104.89,50.37 v1(104.89,50.38) ; v1(51.26,53.91) 51.48,53.91 51.59,53.8 51.84,53.8 52.2,53.44 52.2,52.88 51.64,52.32 51.64,41.99 53.52,40.11 56.09,40.11 56.54,39.65 56.54,39.37 56.6,39.31 J5.188
  LYR6 w0.102: v1(51.26,53.91) 51.48,53.91 51.58,53.81 57.36,53.81 58.19,54.65 61.24,54.65 61.55,54.34 97.36,54.34 100.45,51.25 104.51,51.25 104.79,50.97 104.79,50.7 104.89,50.6 v1(104.89,50.38)
HDMI0_CLK_P1: length 11.6
  BOTTOM w0.095: J9.10 105.7,43.38 105.24,43.84 105.24,44.11 104.97,44.39 104.07,44.39 103.81,44.64 103.81,44.82 103.89,44.9 104.32,44.9 104.39,44.97 104.39,45.14 104.3,45.23 103.93,45.23 103.83,45.33 103.83,45.46 103.93,45.56 104.32,45.56 104.42,45.65 104.42,45.79 104.32,45.88 103.91,45.88 103.81,45.99 103.81,46.2 104.14,46.53 104.14,46.93 104.78,47.56 104.78,47.84 104.89,47.95 U9.4 U9.7 104.89,49.81 L22.1
HDMI0_HOTPLUG: length 54.9
  TOP w0.121: J5.153 63.4,43.39 65.15,45.14 65.15,50.3 v1(65.08,50.38) ; U10.2 U10.9 102.56,46.91 v1(102.42,46.77)
  LYR6 w0.121: v1(65.08,50.38) 65.56,50.86 93.65,50.86 95.76,48.75 97.89,48.75 99.29,47.36 102.06,47.36 102.42,47 v1(102.42,46.77)
  BOTTOM w0.121: J9.19 102.42,44.85 v1(102.42,46.77)
HDMI0_SCL: length 67.6
  TOP w0.121: v1(53.93,39.25) 54.2,38.98 J5.200 ; v1(100.36,47.76) 100.73,47.39 U10.6 ; U10.5 U10.6 ; U10.6 101.06,46.79 102.81,45.04 102.81,42.95 J9.15
  LYR3 w0.121: v1(53.93,39.25) 53.22,39.97 v1(53.22,50.05)
  LYR6 w0.121: v1(100.36,47.76) 99.24,47.76 98,49 95.86,49 93.75,51.11 65.25,51.11 64.95,50.81 53.98,50.81 v1(53.22,50.05)
HDMI0_SDA: length 69.3
  TOP w0.121: v1(53.88,42.4) 53.9,42.4 54.2,42.1 J5.199 ; v1(101.56,46.85) U10.7 U10.4
  LYR3 w0.121: v1(53.88,42.4) 53.88,49.47 v1(53.72,49.62)
  LYR6 w0.121: v1(101.56,46.85) 101.32,47.08 99.21,47.08 97.79,48.5 95.66,48.5 93.55,50.61 66.65,50.61 65.99,49.95 63.15,49.95 62.61,50.48 54.59,50.48 v1(53.72,49.62)
  BOTTOM w0.121: J9.16 102.24,41.59 101.83,41.19 100.74,41.19 99.75,42.18 99.75,43.42 100.18,43.85 100.97,43.85 101.96,44.84 101.96,46.44 v1(101.56,46.85)
HDMI0_TX0_N: length 74.1
  TOP w0.095: J5.184 57.4,39.31 57.46,39.37 57.46,39.96 56.78,40.64 53.86,40.64 52.56,41.95 52.56,51.5 52.44,51.61 v1(52.44,51.83)
  LYR6 w0.102: 52.55,51.83 v1(52.44,51.83) 52.54,51.93 52.54,52.4 52.84,52.69 57.66,52.69 58.6,53.63 60.76,53.63 61.34,53.05 97.06,53.05 100.29,49.82 101.15,49.82 101.27,49.94 101.63,49.94 101.75,49.82 102.72,49.82 102.85,49.94 103.2,49.94 103.33,49.82 103.69,49.82 103.81,49.94 104.17,49.94 104.29,49.82 104.92,49.82 105.05,49.94 105.4,49.94 105.53,49.82 105.88,49.82 105.99,49.92 105.99,50.06 105.88,50.16 v1(105.88,50.38)
HDMI0_TX0_N1: length 8.1
  BOTTOM w0.095: L21.4 105.89,49.85 U9.9 U9.2 105.89,47.97 105.99,47.87 105.99,47.73 105.06,46.8 105.06,45.17 106.58,43.65 106.58,43.24 J9.9
HDMI0_TX0_P: length 74
  TOP w0.095: 106.38,50.37 v1(106.39,50.38) ; v1(52.95,51.83) 52.95,51.61 52.83,51.5 52.83,42.06 53.98,40.92 56.9,40.92 57.74,40.08 57.74,39.37 57.8,39.31 J5.182
  LYR6 w0.102: v1(106.39,50.38) 106.39,50.16 106.29,50.06 106.29,49.79 106.01,49.51 100.16,49.51 96.93,52.74 61.22,52.74 60.63,53.33 58.73,53.33 57.79,52.39 56.82,52.39 56.7,52.26 56.34,52.26 56.21,52.39 55.86,52.39 55.73,52.26 55.37,52.26 55.25,52.39 54.89,52.39 54.76,52.26 54.41,52.26 54.28,52.39 53.93,52.39 53.8,52.26 53.44,52.26 53.32,52.39 52.96,52.39 52.85,52.27 52.85,51.93 v1(52.95,51.83)
HDMI0_TX0_P1: length 10
  BOTTOM w0.095: J9.7 107.29,42.8 106.96,42.8 106.86,42.89 106.86,43.77 105.34,45.29 105.34,45.87 105.43,45.97 105.77,45.97 105.87,46.06 105.87,46.26 105.77,46.35 105.43,46.35 105.34,46.45 105.34,46.68 105.59,46.94 105.73,46.94 105.81,46.85 105.95,46.85 106.08,46.99 106.08,47.12 106,47.21 106,47.34 106.27,47.62 106.27,47.86 106.39,47.98 U9.1 U9.10 106.39,49.85 L21.1
HDMI0_TX1_N: length 69
  TOP w0.095: J5.178 58.6,38.19 58.66,38.13 58.66,37.75 v1(58.55,37.64)
  LYR3 w0.102: v1(58.55,51.78) 58.55,51.56 58.65,51.46 58.65,37.96 58.55,37.86 v1(58.55,37.64)
  LYR6 w0.102: v1(58.55,51.78) 58.55,52 58.65,52.1 58.65,52.37 58.93,52.65 60.25,52.65 60.81,52.08 96.52,52.08 99.9,48.7 103.3,48.7 103.43,48.83 103.79,48.83 103.91,48.7 104.27,48.7 104.4,48.83 104.75,48.83 104.88,48.7 105.67,48.7 105.79,48.83 106.15,48.83 106.28,48.7 106.66,48.7 107.24,49.28 107.24,49.46 107.49,49.72 107.67,49.72 107.92,49.97 107.92,50.62 107.82,50.72 v1(107.82,50.94)
HDMI0_TX1_N1: length 9.7
  BOTTOM w0.095: J9.6 108.01,43.58 106.48,45.11 106.48,46.67 107.93,48.12 107.93,48.48 107.82,48.59 U8.5 U8.6 107.82,50.38 L20.4
HDMI0_TX1_P: length 69
  TOP w0.095: 108.32,50.93 v1(108.33,50.94) ; v1(59.06,37.64) 58.94,37.76 58.94,38.13 59,38.19 J5.176
  LYR3 w0.102: v1(59.06,37.64) 59.06,37.86 58.96,37.96 58.96,51.46 59.06,51.56 v1(59.06,51.78)
  LYR6 w0.102: v1(59.06,51.78) 59.06,52 58.96,52.1 58.96,52.24 59.06,52.34 60.12,52.34 60.68,51.78 61.04,51.78 61.17,51.65 61.52,51.65 61.65,51.78 62,51.78 62.13,51.65 62.49,51.65 62.61,51.78 63.07,51.78 63.2,51.65 63.55,51.65 63.68,51.78 64.04,51.78 64.16,51.65 64.52,51.65 64.65,51.78 96.4,51.78 99.77,48.4 106.78,48.4 108.23,49.84 108.23,50.62 108.33,50.72 v1(108.33,50.94)
